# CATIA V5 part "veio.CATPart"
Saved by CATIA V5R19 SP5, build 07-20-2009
Part number: veio
Bounding box of the stored display mesh (mm): x -8 to 8, y -20 to 20, z -7.954 to 7.954
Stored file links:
  Z:\UA\ATLAS\atlascar\ServoPiloto\dir\suportePotenciometro\V2\potenciometro\veio.CATPart
  Z:\programs_vbox\Dassault Systemes\B19\intel_a\reffiles\standard\MetricThickPitch.txt
  Z:\programs_vbox\Dassault Systemes\B19\intel_a\reffiles\standard\MetricThinPitch.txt
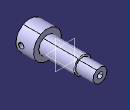
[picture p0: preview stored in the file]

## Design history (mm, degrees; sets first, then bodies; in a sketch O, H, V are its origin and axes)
Body1 (main body)
  Sketch1 on yz-plane, origin (0, 0, 0), H (0, 1, 0), V (0, 0, 1)
    line L1 (-20, 3) -> (-20, 8)
    line L2 (-20, 8) -> (-10, 8)
    line L3 (-10, 8) -> (-10, 5)
    line L4 (-10, 5) -> (10, 5)
    line L5 (20, 4) -> (20, 0)
    point P4 (20, 0)
    line L6 (20, 0) -> (-12, 0)
    line L7 (-12, 0) -> (-12, 3)
    line L8 (-12, 3) -> (-20, 3)
    line L9 (20, 4) -> (10, 4)
    line L10 (10, 4) -> (10, 5)
    distance L6 L8 = 3
    distance L6 L4 = 5
    distance L3 L7 = 2
    distance L5 L3 = 30
    distance L3 L1 = 10
    distance L6 L2 = 8
    distance L5 V = 20 {= (Sketch1.distance(L3 L1) +Sketch1.distance(L5 L3) )/2}
    distance L6 L9 = 4
    distance L5 L10 = 10
    vertical: L1 V, L3 V, L5 V, L7 V, L10 V
    horizontal: L2 H, L4 H, L6 H, L8 H, L9 H
    coincidence: P4 H
  Shaft1: profile Sketch1, axis Sketch1.H, angle 360
  Thread1: "M8", diameter 8, depth 10, pitch 1.25, on face of Shaft1 from Sketch1.L9, from face of Shaft1 from Sketch1.L5
  Sketch2 on face of Shaft1 from Sketch1.L5, origin (0, 20, 0), H (1, 0, 0), V (0, 0, -1)
    point P1 (0, 0)
  Hole1: placed by Sketch2, at (0, 20, 0) direction (0, -1, 0), diameter 3.42, depth 10
  Thread2: "M4", diameter 4, depth 10, pitch 0.7, on face of Hole1, from face of Shaft1 from Sketch1.L5
  Sketch3 on yz-plane, origin (0, 0, 0), H (0, 1, 0), V (0, 0, 1)
    circle A1 centre (-17, 0) radius 1.5
    point P1 (-17, 0)
    reference projected line E1 (-20, 8) -> (-20, -8) from edge [face of Shaft1 from Sketch1.L1 | face of Shaft1 from Sketch1.L2]
    radius A1 = 1.5
    distance P1 E1 = 3
    coincidence: P1 H
  Pocket1: profile Sketch3, direction (-1, 0, 0), through (limit type 6), opposite side through (limit type 6)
